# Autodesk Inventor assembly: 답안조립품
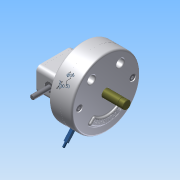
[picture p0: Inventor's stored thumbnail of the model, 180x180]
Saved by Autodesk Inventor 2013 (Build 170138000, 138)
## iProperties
Created: 2015-04
Part Number: 답안조립품
Document SubType Name: Assembly
Designer: Administrator
Author: Administrator
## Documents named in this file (15)
- C:\Documents and Settings\Administrator\바탕 화면\350405V1022\답안조립품.iam
- C:\Documents and Settings\Administrator\바탕 화면\350405V1022\본체.ipt
- C:\Documents and Settings\Administrator\바탕 화면\350405V1022\커버2.ipt
- C:\Documents and Settings\Administrator\바탕 화면\350405V1022\베어링62_22.ipt
- C:\Documents and Settings\Administrator\바탕 화면\350405V1022\축.ipt
- C:\Documents and Settings\Administrator\바탕 화면\350405V1022\M 5 x 12.ipt
- C:\Documents and Settings\Administrator\바탕 화면\350405V1022\부시.ipt
- C:\Documents and Settings\Administrator\바탕 화면\350405V1022\슬라이더3.ipt
- C:\Documents and Settings\Administrator\바탕 화면\350405V1022\슬라이더2.ipt
- C:\Documents and Settings\Administrator\바탕 화면\350405V1022\멈춤링.ipt
- C:\Documents and Settings\Administrator\바탕 화면\350405V1022\슬라이더.ipt
- C:\Documents and Settings\Administrator\바탕 화면\350405V1022\평행핀.ipt
- C:\Documents and Settings\Administrator\바탕 화면\350405V1022\커버.ipt
- C:\Documents and Settings\Administrator\바탕 화면\350405V1022\M 10 x 35.ipt
- C:\Documents and Settings\Administrator\바탕 화면\350405V1022\가변스프링.ipt
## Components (6 placed, 4 different names)
1. M 5 x 12:1
2. M 5 x 12:2
3. KS B 1320 B B 5 x  20:1 — 플러쉬:2
4. M 10 x 35:1
5. M 10 x 35:2
6. 가변스프링:1
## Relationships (1: Flush 1)
- 플러쉬:2 [Flush]: KS B 1320 B B 5 x  20:1
